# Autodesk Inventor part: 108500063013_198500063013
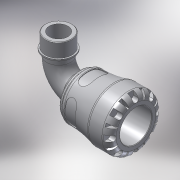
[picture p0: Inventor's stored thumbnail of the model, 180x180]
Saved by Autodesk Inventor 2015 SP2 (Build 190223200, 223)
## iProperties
Created: 2016-12
Part Number: 108500063013_198500063013
Material: PVC-Piping
Description: PLASSON 90° ELBOW WITH THREADED MALE OFFTAKE 63-1.1/4" SERIES 1
Document SubType Name: Modeling
Designer: KIM
Mass: 678.209 g
Surface Area: 851.511 cm^2
Volume: 484.435 cm^3
Density: 1.4 g/cm^3
Appearance: Smooth - White
Author: KIM
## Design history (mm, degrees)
derived "1085.ipt"
feature "Solid1::1085.ipt"
tag "TaggingFeature1"
body "Solid1"
other parameters: "d1" = 37.8, "d2" = 63, "d3" = 78.75, "d4" = 103, "d8" = 87.55, "d13" = 9.7, "d14" = 9.7, "d15" = 0, "d17" = 360 deg, "d19" = 8 deg, "d20" = 1.26, "d21" = 1.26, "d22" = 8 deg, "d24" = 0, "d26" = 360 deg, "d33" = 10.3, "d43" = 80.34, "d51" = 1.03, "d54" = 22.05, "d55" = 13.86, "d57" = 19.012, "d58" = 0, "d74" = 0, "d82" = 1.26, "d115" = 360 deg, "d207" = 90 deg, "d228" = 18.7425, "d247" = 2.06, "d248" = 5.4, "d268" = 48.1525, "d269" = 5.4, "d270" = 143, "d276" = 41.91, "d277" = 22, "d278" = 46.101, "d279" = 76, "d280" = 24.2, "d281" = 6.2865, "d283" = 37.719, "d286" = 0, "d287" = 0, "d288" = 29.337, "d290" = 21.3105, "d292" = 30 deg, "d_" = 63, "E_" = 103, "A_" = 143, "A_1" = 76, "l_2" = 22, "R_" = 41.91, "d9" = 12.125, "d11" = 103, "d12" = 78.75, "d289" = 29.337
